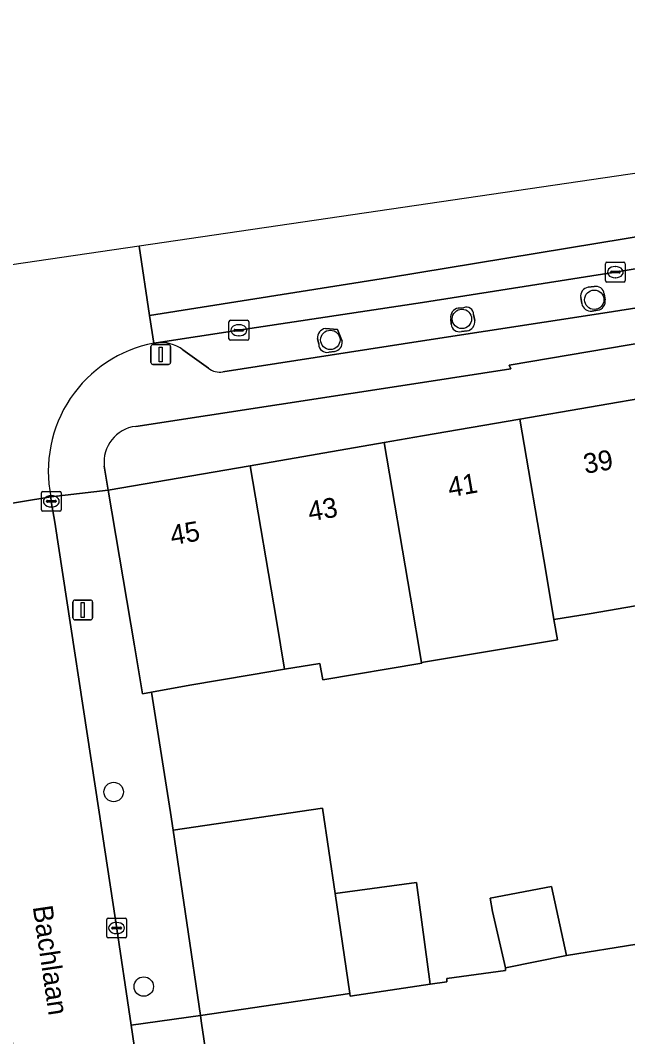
# Model space of a CAD drawing. Extents: x 159053 to 160042, y 380449 to 381423.
# Drawn here: x 159479.7 to 159510.3, y 381270.9 to 381322.1 of the extents above; entities that cross this region are included whole.
import ezdxf

# ---------------------------------------------------------------- set-up
doc = ezdxf.new("R2010")
doc.units = 0
for name, color, linetype in [('IMGEO_Boom', 7, 'Continuous'), ('IMGEO_Erf', 7, 'Continuous'), ('IMGEO_Inrit_open', 7, 'Continuous'), ('IMGEO_Kolk', 7, 'Continuous'), ('IMGEO_Lichtmast', 7, 'Continuous'), ('IMGEO_Muur', 7, 'Continuous'), ('IMGEO_Openbare_ruimte_label', 7, 'Continuous'), ('IMGEO_Pand', 7, 'Continuous'), ('IMGEO_Pand_nummerreeks', 7, 'Continuous'), ('IMGEO_Parkeervlak_open', 7, 'Continuous'), ('IMGEO_Rijbaan_lokaal_gesloten', 7, 'Continuous'), ('IMGEO_Rijbaan_lokaal_open', 7, 'Continuous'), ('IMGEO_Verkeerseiland_groen', 7, 'Continuous'), ('IMGEO_Voetpad_open', 7, 'Continuous')]:
    doc.layers.add(name, color=color, linetype=linetype)

msp = doc.modelspace()

# ---------------------------------------------------------------- linework, layer by layer
at = {"layer": 'IMGEO_Boom'}
for centre in [(159508.66, 381308.02), (159501.99, 381307.056), (159495.358, 381305.998), (159484.438, 381283.217), (159485.954, 381273.411)]:
    msp.add_circle(centre, 0.489, dxfattribs=at)
at = {"layer": 'IMGEO_Erf'}
for points in [[(159552.705, 381313.429), (159543.626, 381311.785), (159523.095, 381307.767), (159523.841, 381302.802), (159524.139, 381300.817), (159518.944, 381300.036), (159522.619, 381293.167), (159523.897, 381291.098), (159521.161, 381289.363), (159519.673, 381291.562), (159515.422, 381299.507), (159514.383, 381306.418), (159504.373, 381304.731), (159504.45, 381304.533), (159500, 381303.852), (159485.55, 381301.639)], [(159483.965, 381299.633), (159484.164, 381298.42), (159491.31, 381299.654), (159498.078, 381300.823), (159500, 381301.155), (159504.914, 381302.005), (159511.926, 381303.217)], [(159511.217, 381292.673), (159508.407, 381292.2), (159506.629, 381291.901), (159506.799, 381290.889), (159499.957, 381289.739), (159499.963, 381289.705), (159494.973, 381288.866), (159494.833, 381289.697), (159493.055, 381289.398), (159491.37, 381289.115), (159488.272, 381288.594), (159486.347, 381288.247), (159487.299, 381282.186), (159487.432, 381281.286), (159494.97, 381282.402), (159495.606, 381278.108), (159499.699, 381278.661), (159500.381, 381273.53), (159501.233, 381273.658), (159501.223, 381273.823), (159504.187, 381274.222), (159504.186, 381274.353), (159503.534, 381277.198), (159503.405, 381277.859), (159506.504, 381278.46), (159507.252, 381274.976), (159510.808, 381275.554)]]:
    msp.add_lwpolyline(points, dxfattribs=at)
msp.add_arc((159485.765, 381299.84), 1.812, 96.8041, 186.5693, dxfattribs=at)
at = {"layer": 'IMGEO_Inrit_open'}
msp.add_lwpolyline([(159488.87, 381271.571), (159488.814, 381271.948), (159485.313, 381271.467), (159486.141, 381265.894), (159489.62, 381266.493)], close=True, dxfattribs=at)
at = {"layer": 'IMGEO_Kolk'}
for p, q in [((159509.221, 381308.985), (159509.221, 381309.837)), ((159509.296, 381309.911), (159510.148, 381309.911)), ((159509.523, 381309.454), (159509.921, 381309.454)), ((159509.709, 381309.691), (159509.734, 381309.691)), ((159510.222, 381309.837), (159510.222, 381308.985)), ((159509.48, 381309.405), (159509.48, 381309.417)), ((159509.918, 381309.368), (159509.52, 381309.368)), ((159509.732, 381309.131), (159509.707, 381309.131)), ((159509.964, 381309.417), (159509.964, 381309.405)), ((159510.148, 381308.911), (159509.296, 381308.911)), ((159490.246, 381306.058), (159490.246, 381306.91)), ((159490.321, 381306.984), (159491.173, 381306.984)), ((159491.247, 381306.91), (159491.247, 381306.058)), ((159490.505, 381306.478), (159490.505, 381306.49)), ((159490.943, 381306.441), (159490.545, 381306.441)), ((159490.548, 381306.527), (159490.946, 381306.527)), ((159490.734, 381306.764), (159490.759, 381306.764)), ((159490.989, 381306.49), (159490.989, 381306.478)), ((159491.173, 381305.984), (159490.321, 381305.984)), ((159490.757, 381306.204), (159490.732, 381306.204)), ((159480.797, 381297.436), (159480.797, 381298.288)), ((159480.872, 381298.362), (159481.724, 381298.362)), ((159481.798, 381298.288), (159481.798, 381297.436)), ((159481.056, 381297.856), (159481.056, 381297.868)), ((159481.494, 381297.819), (159481.096, 381297.819)), ((159481.099, 381297.905), (159481.497, 381297.905)), ((159481.285, 381298.142), (159481.31, 381298.142)), ((159481.54, 381297.868), (159481.54, 381297.856)), ((159481.724, 381297.362), (159480.872, 381297.362)), ((159481.308, 381297.582), (159481.283, 381297.582)), ((159484.086, 381275.935), (159484.086, 381276.787)), ((159484.161, 381276.861), (159485.013, 381276.861)), ((159485.087, 381276.787), (159485.087, 381275.935)), ((159484.345, 381276.355), (159484.345, 381276.367)), ((159484.783, 381276.318), (159484.385, 381276.318)), ((159484.388, 381276.404), (159484.786, 381276.404)), ((159484.574, 381276.641), (159484.599, 381276.641)), ((159484.829, 381276.367), (159484.829, 381276.355)), ((159485.013, 381275.861), (159484.161, 381275.861)), ((159484.597, 381276.081), (159484.572, 381276.081))]:
    msp.add_line(p, q, dxfattribs=at)
for points in [[(159509.221, 381308.985), (159509.221, 381309.837)], [(159509.296, 381309.911), (159510.148, 381309.911)], [(159510.222, 381309.837), (159510.222, 381308.985)], [(159510.148, 381308.911), (159509.296, 381308.911)], [(159490.246, 381306.058), (159490.246, 381306.91)], [(159490.321, 381306.984), (159491.173, 381306.984)], [(159491.247, 381306.91), (159491.247, 381306.058)], [(159491.173, 381305.984), (159490.321, 381305.984)], [(159480.797, 381297.436), (159480.797, 381298.288)], [(159480.872, 381298.362), (159481.724, 381298.362)], [(159481.798, 381298.288), (159481.798, 381297.436)], [(159481.724, 381297.362), (159480.872, 381297.362)], [(159484.086, 381275.935), (159484.086, 381276.787)], [(159484.161, 381276.861), (159485.013, 381276.861)], [(159485.087, 381276.787), (159485.087, 381275.935)], [(159485.013, 381275.861), (159484.161, 381275.861)]]:
    msp.add_lwpolyline(points, dxfattribs=at)
for centre, radius, start, end in [((159509.298, 381309.835), 0.0765, 91.552, 178.448), ((159509.298, 381309.835), 0.0765, 91.552, 178.448), ((159509.52, 381309.414), 0.0403, 85.8775, 175.7526), ((159509.925, 381309.416), 0.0386, 1.7309, 96.639), ((159510.146, 381309.835), 0.0765, 1.552, 88.448), ((159510.146, 381309.835), 0.0765, 1.552, 88.448), ((159509.298, 381308.987), 0.0765, 181.552, 268.448), ((159509.298, 381308.987), 0.0765, 181.552, 268.448), ((159509.517, 381309.404), 0.0366, 178.938, 274.7102), ((159509.921, 381309.411), 0.043, 264.8664, 352.4533), ((159510.146, 381308.987), 0.0765, 271.552, 358.448), ((159510.146, 381308.987), 0.0765, 271.552, 358.448), ((159490.323, 381306.908), 0.0765, 91.552, 178.448), ((159490.323, 381306.908), 0.0765, 91.552, 178.448), ((159491.171, 381306.908), 0.0765, 1.552, 88.448), ((159491.171, 381306.908), 0.0765, 1.552, 88.448), ((159490.545, 381306.487), 0.0403, 85.8775, 175.7526), ((159490.542, 381306.477), 0.0366, 178.938, 274.7102), ((159490.946, 381306.484), 0.043, 264.8664, 352.4533), ((159490.95, 381306.489), 0.0386, 1.7309, 96.639), ((159490.323, 381306.06), 0.0765, 181.552, 268.448), ((159490.323, 381306.06), 0.0765, 181.552, 268.448), ((159491.171, 381306.06), 0.0765, 271.552, 358.448), ((159491.171, 381306.06), 0.0765, 271.552, 358.448), ((159480.874, 381298.286), 0.0765, 91.552, 178.448), ((159480.874, 381298.286), 0.0765, 91.552, 178.448), ((159481.722, 381298.286), 0.0765, 1.552, 88.448), ((159481.722, 381298.286), 0.0765, 1.552, 88.448), ((159481.096, 381297.865), 0.0403, 85.8775, 175.7526), ((159481.093, 381297.855), 0.0366, 178.938, 274.7102), ((159481.497, 381297.862), 0.043, 264.8664, 352.4533), ((159481.501, 381297.867), 0.0386, 1.7309, 96.639), ((159480.874, 381297.438), 0.0765, 181.552, 268.448), ((159480.874, 381297.438), 0.0765, 181.552, 268.448), ((159481.722, 381297.438), 0.0765, 271.552, 358.448), ((159481.722, 381297.438), 0.0765, 271.552, 358.448), ((159484.163, 381276.785), 0.0765, 91.552, 178.448), ((159484.163, 381276.785), 0.0765, 91.552, 178.448), ((159485.011, 381276.785), 0.0765, 1.552, 88.448), ((159485.011, 381276.785), 0.0765, 1.552, 88.448), ((159484.385, 381276.364), 0.0403, 85.8775, 175.7526), ((159484.382, 381276.354), 0.0366, 178.938, 274.7102), ((159484.786, 381276.361), 0.043, 264.8664, 352.4533), ((159484.79, 381276.366), 0.0386, 1.7309, 96.639), ((159484.163, 381275.937), 0.0765, 181.552, 268.448), ((159484.163, 381275.937), 0.0765, 181.552, 268.448), ((159485.011, 381275.937), 0.0765, 271.552, 358.448), ((159485.011, 381275.937), 0.0765, 271.552, 358.448)]:
    msp.add_arc(centre, radius, start, end, dxfattribs=at)
for centre, major_axis, ratio, start_param, end_param in [((159509.708, 381309.411), (-0.387, 0.002), 0.722429, 4.712389, 7.853982), ((159509.733, 381309.411), (-0.39, 0.002), 0.717154, 1.570796, 4.712389), ((159490.733, 381306.484), (-0.387, 0.002), 0.722429, 4.712389, 7.853982), ((159490.758, 381306.484), (-0.39, 0.002), 0.717154, 1.570796, 4.712389), ((159481.284, 381297.862), (-0.387, 0.002), 0.722429, 4.712389, 7.853982), ((159481.309, 381297.862), (-0.39, 0.002), 0.717154, 1.570796, 4.712389), ((159484.573, 381276.361), (-0.387, 0.002), 0.722429, 4.712389, 7.853982), ((159484.598, 381276.361), (-0.39, 0.002), 0.717154, 1.570796, 4.712389)]:
    msp.add_ellipse(centre, major_axis=major_axis, ratio=ratio, start_param=start_param, end_param=end_param, dxfattribs=at)
at = {"layer": 'IMGEO_Lichtmast'}
for p, q in [((159486.312, 381304.861), (159486.312, 381305.661)), ((159486.312, 381305.661), (159486.312, 381304.861)), ((159486.412, 381305.761), (159487.202, 381305.761)), ((159487.202, 381305.761), (159486.412, 381305.761)), ((159487.302, 381305.661), (159487.302, 381304.861)), ((159487.302, 381304.861), (159487.302, 381305.661)), ((159487.202, 381304.761), (159486.412, 381304.761)), ((159486.412, 381304.761), (159487.202, 381304.761)), ((159482.383, 381291.989), (159482.383, 381292.789)), ((159482.383, 381292.789), (159482.383, 381291.989)), ((159482.483, 381292.889), (159483.273, 381292.889)), ((159483.273, 381292.889), (159482.483, 381292.889)), ((159483.373, 381292.789), (159483.373, 381291.989)), ((159483.373, 381291.989), (159483.373, 381292.789)), ((159483.273, 381291.889), (159482.483, 381291.889)), ((159482.483, 381291.889), (159483.273, 381291.889))]:
    msp.add_line(p, q, dxfattribs=at)
for points in [[(159486.732, 381305.636), (159486.882, 381305.636), (159486.882, 381304.886), (159486.732, 381304.886), (159486.732, 381305.636)], [(159482.803, 381292.764), (159482.953, 381292.764), (159482.953, 381292.014), (159482.803, 381292.014), (159482.803, 381292.764)]]:
    msp.add_lwpolyline(points, dxfattribs=at)
for centre, start, end in [((159486.412, 381305.661), 90, 180), ((159486.412, 381305.661), 90, 180), ((159487.202, 381305.661), 0, 90), ((159487.202, 381305.661), 360, 90), ((159486.412, 381304.861), 180, 270), ((159486.412, 381304.861), 180, 270), ((159487.202, 381304.861), 270, 0), ((159487.202, 381304.861), 270, 0), ((159482.483, 381292.789), 90, 180), ((159482.483, 381292.789), 90, 180), ((159483.273, 381292.789), 0, 90), ((159483.273, 381292.789), 360, 90), ((159482.483, 381291.989), 180, 270), ((159482.483, 381291.989), 180, 270), ((159483.273, 381291.989), 270, 0), ((159483.273, 381291.989), 270, 0)]:
    msp.add_arc(centre, 0.1, start, end, dxfattribs=at)
at = {"layer": 'IMGEO_Muur'}
msp.add_lwpolyline([(159486.347, 381288.247), (159487.299, 381282.186)], dxfattribs=at)
at = {"layer": 'IMGEO_Pand'}
for points in [[(159504.914, 381302.005), (159506.236, 381294.238), (159506.629, 381291.901), (159508.407, 381292.2), (159511.217, 381292.673), (159510.835, 381294.941), (159513.272, 381295.351), (159512.769, 381298.289), (159511.926, 381303.217)], [(159504.914, 381302.005), (159500, 381301.155), (159498.078, 381300.823), (159499.403, 381293.037), (159499.957, 381289.739), (159506.799, 381290.889), (159506.629, 381291.901), (159506.236, 381294.238)], [(159498.078, 381300.823), (159491.31, 381299.654), (159492.638, 381291.851), (159493.055, 381289.398), (159494.833, 381289.697), (159494.973, 381288.866), (159499.963, 381289.705), (159499.957, 381289.739), (159499.403, 381293.037)], [(159491.31, 381299.654), (159484.164, 381298.42), (159485.491, 381290.577), (159485.899, 381288.166), (159486.347, 381288.247), (159488.272, 381288.594), (159491.37, 381289.115), (159493.055, 381289.398), (159492.638, 381291.851)], [(159495.606, 381278.108), (159494.97, 381282.402), (159487.432, 381281.286), (159488.814, 381271.948), (159496.334, 381273.061)], [(159495.606, 381278.108), (159496.334, 381273.061), (159496.356, 381272.925), (159500.381, 381273.53), (159499.699, 381278.661)], [(159504.186, 381274.353), (159507.252, 381274.976), (159506.504, 381278.46), (159503.405, 381277.859), (159503.534, 381277.198)]]:
    msp.add_lwpolyline(points, close=True, dxfattribs=at)
at = {"layer": 'IMGEO_Parkeervlak_open'}
for points in [[(159552.716, 381317.04), (159549.389, 381316.39), (159539.699, 381314.595), (159531.204, 381313.075), (159521.192, 381311.328), (159509.718, 381309.412), (159500, 381307.878), (159490.742, 381306.485), (159486.58, 381305.853)], [(159489.945, 381304.382), (159500, 381305.941), (159509.315, 381307.385), (159514.749, 381308.232), (159521.67, 381309.407), (159525.666, 381310.076), (159536.032, 381311.918)], [(159508.357, 381308.647), (159508.647, 381308.679)], [(159508.03, 381307.825), (159507.979, 381308.126)], [(159509.16, 381308.318), (159509.204, 381308.018)], [(159501.797, 381307.601), (159502.075, 381307.617)], [(159508.828, 381307.493), (159508.551, 381307.446)], [(159501.448, 381306.784), (159501.423, 381307.066)], [(159502.581, 381307.27), (159502.633, 381306.977)], [(159495.108, 381306.571), (159495.711, 381306.525), (159495.954, 381305.925)], [(159502.257, 381306.452), (159501.961, 381306.421)], [(159494.771, 381305.779), (159494.71, 381306.059)], [(159487.932, 381305.496), (159489.211, 381304.57)], [(159495.575, 381305.416), (159495.281, 381305.382)]]:
    msp.add_lwpolyline(points, dxfattribs=at)
for centre, radius, start, end in [((159508.405, 381308.214), 0.435, 96.3879, 191.6883), ((159508.739, 381308.265), 0.424, 7.1926, 102.539), ((159508.767, 381307.934), 0.445, 277.8835, 10.8967), ((159501.891, 381307.137), 0.474, 101.4931, 188.5947), ((159502.215, 381307.279), 0.366, 358.5604, 112.5572), ((159508.486, 381307.905), 0.463, 189.9153, 278.0169), ((159502.166, 381306.914), 0.471, 281.1612, 7.619), ((159495.18, 381306.105), 0.472, 98.7462, 185.5348), ((159501.855, 381306.815), 0.408, 184.3494, 285.084), ((159486.804, 381303.961), 1.905, 53.6799, 96.737), ((159495.504, 381305.864), 0.454, 278.9872, 7.6703), ((159495.177, 381305.775), 0.406, 179.4141, 284.7893), ((159489.789, 381305.3), 0.931, 231.6345, 279.6327)]:
    msp.add_arc(centre, radius, start, end, dxfattribs=at)
at = {"layer": 'IMGEO_Rijbaan_lokaal_gesloten'}
msp.add_lwpolyline([(159485.73, 381310.724), (159485.73, 381310.724), (159486.249, 381307.229), (159498.232, 381309.125), (159519.334, 381312.605), (159537.334, 381315.754), (159551.245, 381318.435), (159564.404, 381321.209), (159579.772, 381324.783), (159593.307, 381328.356), (159605.338, 381331.789), (159626.628, 381338.418), (159649.891, 381345.846), (159673.107, 381353.416), (159685.932, 381357.579), (159685.204, 381359.893), (159670.766, 381354.293), (159597.865, 381331.733), (159554.111, 381320.745)], close=True, dxfattribs=at)
for points in [[(159564.404, 381321.209), (159551.245, 381318.435), (159537.334, 381315.754), (159519.334, 381312.605), (159498.232, 381309.125), (159486.249, 381307.229), (159486.456, 381305.834), (159486.58, 381305.853), (159490.742, 381306.485), (159500, 381307.878), (159509.718, 381309.412), (159521.192, 381311.328), (159531.204, 381313.075), (159539.699, 381314.595), (159549.389, 381316.39), (159552.716, 381317.04), (159552.829, 381317.062), (159570.995, 381321.057)], [(159486.456, 381305.834), (159486.249, 381307.229), (159485.73, 381310.724), (159485.73, 381310.724), (159476.646, 381309.393), (159471.77, 381308.678), (159466.939, 381307.675)], [(159475.222, 381297.865), (159475.346, 381297.113), (159481.275, 381298.091)]]:
    msp.add_lwpolyline(points, dxfattribs=at)
msp.add_arc((159487.708, 381299.392), 6.563, 100.9941, 191.4313, dxfattribs=at)
at = {"layer": 'IMGEO_Rijbaan_lokaal_open'}
msp.add_lwpolyline([(159485.313, 381271.467), (159484.524, 381276.78), (159484.001, 381280.293), (159483.708, 381282.207), (159481.469, 381296.819), (159481.293, 381297.861), (159481.275, 381298.091), (159475.346, 381297.113), (159475.58, 381295.695), (159475.809, 381294.223), (159476.504, 381289.652), (159478.964, 381273.094), (159479.515, 381269.384), (159480.289, 381264.217), (159486.258, 381265.111), (159486.141, 381265.894)], close=True, dxfattribs=at)
msp.add_lwpolyline([(159538.088, 381270.011), (159530.524, 381278.017), (159526.41, 381277.349), (159515.623, 381275.597), (159510.925, 381274.834), (159510.808, 381275.554), (159507.252, 381274.976), (159504.186, 381274.353), (159504.187, 381274.222), (159501.223, 381273.823), (159501.233, 381273.658), (159500.381, 381273.53), (159496.356, 381272.925), (159496.334, 381273.061), (159488.814, 381271.948), (159488.87, 381271.571), (159489.62, 381266.493)], dxfattribs=at)
at = {"layer": 'IMGEO_Verkeerseiland_groen'}
for points in [[(159508.647, 381308.679), (159508.357, 381308.647)], [(159507.979, 381308.126), (159508.03, 381307.825)], [(159509.204, 381308.018), (159509.16, 381308.318)], [(159502.075, 381307.617), (159501.797, 381307.601)], [(159508.551, 381307.446), (159508.828, 381307.493)], [(159501.423, 381307.066), (159501.448, 381306.784)], [(159502.633, 381306.977), (159502.581, 381307.27)], [(159495.711, 381306.525), (159495.108, 381306.571)], [(159495.954, 381305.925), (159495.711, 381306.525)], [(159501.961, 381306.421), (159502.257, 381306.452)], [(159494.71, 381306.059), (159494.771, 381305.779)], [(159495.281, 381305.382), (159495.575, 381305.416)]]:
    msp.add_lwpolyline(points, dxfattribs=at)
for centre, radius, start, end in [((159508.405, 381308.214), 0.435, 96.3879, 191.6883), ((159508.739, 381308.265), 0.424, 7.1926, 102.539), ((159508.767, 381307.934), 0.445, 277.8835, 10.8967), ((159501.891, 381307.137), 0.474, 101.4931, 188.5947), ((159502.215, 381307.279), 0.366, 358.5604, 112.5572), ((159508.486, 381307.905), 0.463, 189.9153, 278.0169), ((159502.166, 381306.914), 0.471, 281.1612, 7.619), ((159495.18, 381306.105), 0.472, 98.7462, 185.5348), ((159501.855, 381306.815), 0.408, 184.3494, 285.084), ((159495.504, 381305.864), 0.454, 278.9872, 7.6703), ((159495.177, 381305.775), 0.406, 179.4141, 284.7893)]:
    msp.add_arc(centre, radius, start, end, dxfattribs=at)
at = {"layer": 'IMGEO_Voetpad_open'}
for points in [[(159485.55, 381301.639), (159500, 381303.852), (159504.45, 381304.533), (159504.373, 381304.731), (159514.383, 381306.418), (159523.095, 381307.767), (159543.626, 381311.785), (159552.705, 381313.429), (159558.748, 381314.525)], [(159536.032, 381311.918), (159525.666, 381310.076), (159521.67, 381309.407), (159514.749, 381308.232), (159509.315, 381307.385), (159500, 381305.941), (159489.945, 381304.382)], [(159486.58, 381305.853), (159486.456, 381305.834)], [(159489.211, 381304.57), (159487.932, 381305.496)], [(159481.275, 381298.091), (159482.708, 381298.254), (159484.164, 381298.42), (159483.965, 381299.633)]]:
    msp.add_lwpolyline(points, dxfattribs=at)
msp.add_lwpolyline([(159486.347, 381288.247), (159485.899, 381288.166), (159485.491, 381290.577), (159484.164, 381298.42), (159482.708, 381298.254), (159481.275, 381298.091), (159481.293, 381297.861), (159481.469, 381296.819), (159483.708, 381282.207), (159484.001, 381280.293), (159484.524, 381276.78), (159485.313, 381271.467), (159488.814, 381271.948), (159487.432, 381281.286), (159487.299, 381282.186)], close=True, dxfattribs=at)
for centre, radius, start, end in [((159486.804, 381303.961), 1.905, 53.6799, 96.737), ((159487.708, 381299.392), 6.563, 100.9941, 191.4313), ((159489.789, 381305.3), 0.931, 231.6345, 279.6327), ((159485.765, 381299.84), 1.812, 96.8041, 186.5693)]:
    msp.add_arc(centre, radius, start, end, dxfattribs=at)

# ---------------------------------------------------------------- texts
at = {"layer": 'IMGEO_Openbare_ruimte_label'}
msp.add_text('Bachlaan', height=1, rotation=278.3976, dxfattribs=at).set_placement((159480.357, 381277.432))
at = {"layer": 'IMGEO_Pand_nummerreeks'}
for s, p in [('39', (159508.201, 381299.244)), ('41', (159501.371, 381298.064)), ('43', (159494.32, 381296.845)), ('45', (159487.379, 381295.646))]:
    msp.add_text(s, height=1, rotation=9.8033, dxfattribs=at).set_placement(p)

doc.saveas('drawing.dxf')
